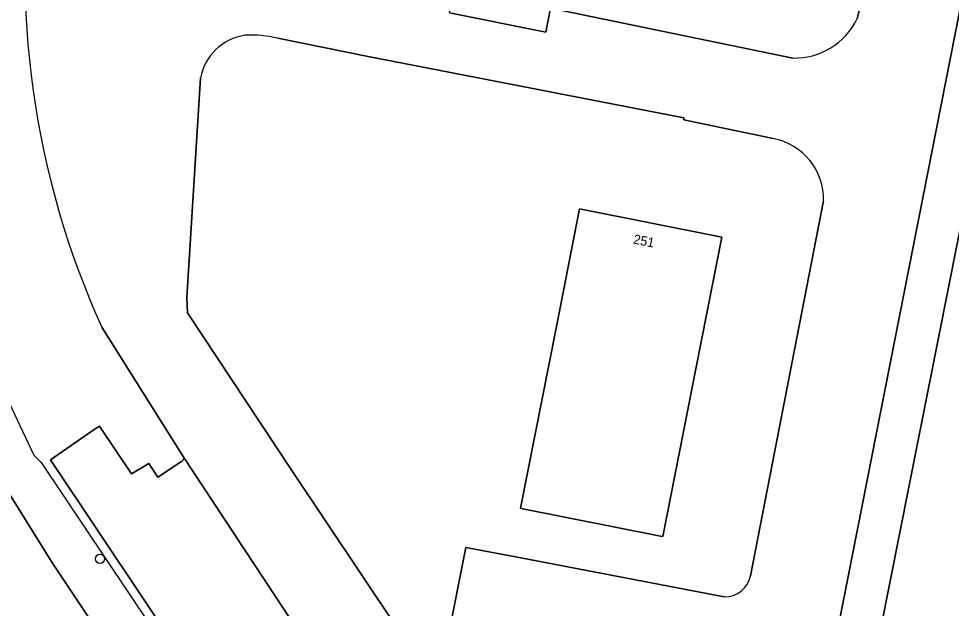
# Model space of a CAD drawing. Extents: x 158793 to 159888, y 384317 to 385256.
# Drawn here: x 159294 to 159393, y 384641.8 to 384704.4 of the extents above; entities that cross this region are included whole.
import ezdxf

# ---------------------------------------------------------------- set-up
doc = ezdxf.new("R2010")
doc.units = 0
for name, color, linetype in [('IMGEO_Berm_groen', 7, 'Continuous'), ('IMGEO_Boom', 7, 'Continuous'), ('IMGEO_Erf', 7, 'Continuous'), ('IMGEO_Groenvoorziening', 7, 'Continuous'), ('IMGEO_Hek', 7, 'Continuous'), ('IMGEO_Pand', 7, 'Continuous'), ('IMGEO_Pand_nummerreeks', 7, 'Continuous'), ('IMGEO_Parkeervlak_open', 7, 'Continuous'), ('IMGEO_Rijbaan_lokaal_gesloten', 7, 'Continuous'), ('IMGEO_Voetpad_open', 7, 'Continuous')]:
    doc.layers.add(name, color=color, linetype=linetype)

msp = doc.modelspace()

# ---------------------------------------------------------------- linework, layer by layer
at = {"layer": 'IMGEO_Berm_groen'}
msp.add_lwpolyline([(159333.494, 384583.345), (159340.335, 384575.84), (159343.091, 384578.482), (159297.497, 384646.725), (159292.522, 384654.756), (159285.647, 384666.91), (159278.91, 384680.193)], dxfattribs=at)
at = {"layer": 'IMGEO_Boom'}
msp.add_circle((159302.631, 384647.073), 0.489, dxfattribs=at)
at = {"layer": 'IMGEO_Erf'}
for points in [[(159374.089, 384691.673), (159364.589, 384693.665), (159364.601, 384693.879), (159331.106, 384700.379), (159321.51, 384702.312)], [(159313.29, 384698.113), (159311.832, 384674.807)], [(159371.682, 384645.285), (159379.439, 384685.054)], [(159311.832, 384674.807), (159311.915, 384673.194), (159322.922, 384656.565), (159337.783, 384634.349)], [(159338.72, 384634.515), (159341.448, 384648.274), (159346.548, 384647.313), (159368.894, 384643.043)]]:
    msp.add_lwpolyline(points, dxfattribs=at)
msp.add_lwpolyline([(159351.107, 384671.91), (159353.529, 384684.2), (159368.63, 384681.21), (159367.146, 384673.684), (159366.373, 384669.762), (159362.366, 384649.444), (159362.14, 384649.489), (159347.5, 384652.39), (159347.269, 384652.44)], close=True, dxfattribs=at)
for centre, radius, start, end in [((159318.85, 384697.015), 5.667, 98.5115, 168.83156), ((159318.695, 384690.356), 12.283, 76.74869, 93.1903), ((159372.885, 384685.228), 6.556, 358.47607, 79.4197), ((159368.964, 384645.81), 2.768, 268.55001, 349.05974)]:
    msp.add_arc(centre, radius, start, end, dxfattribs=at)
at = {"layer": 'IMGEO_Groenvoorziening'}
for points in [[(159259.345, 384775.845), (159258.476, 384779.062), (159246.475, 384781.347), (159238.159, 384778.066), (159249.737, 384750), (159261.949, 384720.397), (159274.24, 384690.602), (159274.429, 384690.144), (159278.91, 384680.193), (159285.647, 384666.91), (159292.522, 384654.756), (159297.497, 384646.725), (159343.091, 384578.482), (159343.747, 384579.11), (159344.133, 384578.71), (159340.698, 384575.458), (159343.371, 384572.63)], [(159311.46, 384657.947), (159302.815, 384671.649)], [(159361.521, 384557.604), (159362.312, 384556.684), (159363.352, 384557.381), (159364.038, 384557.841), (159360.749, 384562.76), (159347.62, 384582.396), (159327.44, 384612.577), (159297.356, 384657.569), (159302.122, 384660.871), (159302.57, 384661.155), (159305.956, 384656.085), (159307.806, 384657.199), (159308.755, 384655.741), (159311.27, 384657.413)]]:
    msp.add_lwpolyline(points, dxfattribs=at)
for centre, radius, start, end in [((159385.86, 384709.379), 91.215, 171.46871, 204.43394), ((159311.158, 384657.754), 0.359, 288.25757, 32.57078)]:
    msp.add_arc(centre, radius, start, end, dxfattribs=at)
at = {"layer": 'IMGEO_Hek'}
msp.add_lwpolyline([(159274.5, 384690.739), (159278.929, 384692.559), (159288.519, 384672.14), (159291.739, 384666.179), (159295.6, 384658.09), (159296.39, 384657.309), (159363.352, 384557.381)], dxfattribs=at)
at = {"layer": 'IMGEO_Pand'}
for points in [[(159339.73, 384705), (159349.94, 384702.969), (159350.44, 384705.486)], [(159396.73, 384696.179), (159374.239, 384582.909), (159398.809, 384578.09)]]:
    msp.add_lwpolyline(points, dxfattribs=at)
msp.add_lwpolyline([(159366.373, 384669.762), (159367.146, 384673.684), (159368.63, 384681.21), (159353.529, 384684.2), (159351.107, 384671.91), (159347.269, 384652.44), (159347.5, 384652.39), (159362.14, 384649.489), (159362.366, 384649.444)], close=True, dxfattribs=at)
at = {"layer": 'IMGEO_Parkeervlak_open'}
for points in [[(159375.084, 384714.387), (159376.059, 384719.309), (159366.249, 384721.252), (159354.049, 384723.669), (159350.44, 384705.486), (159376.165, 384700.213)], [(159382.997, 384704.388), (159384.634, 384710.887)], [(159311.27, 384657.413), (159308.755, 384655.741), (159307.806, 384657.199), (159305.956, 384656.085), (159302.57, 384661.155), (159302.122, 384660.871), (159297.356, 384657.569), (159327.44, 384612.577), (159333.099, 384616.361), (159333.285, 384616.081), (159365.154, 384567.946), (159369.445, 384561.464), (159372.753, 384556.485), (159383.254, 384540.805), (159386.325, 384542.862), (159387.316, 384543.526)], [(159355.537, 384591.604), (159337.281, 384618.767), (159311.46, 384657.947)]]:
    msp.add_lwpolyline(points, dxfattribs=at)
for centre, radius, start, end in [((159376.38, 384707.539), 7.329, 268.31979, 334.53799), ((159311.158, 384657.754), 0.359, 288.25757, 32.57078)]:
    msp.add_arc(centre, radius, start, end, dxfattribs=at)
at = {"layer": 'IMGEO_Rijbaan_lokaal_gesloten'}
for points in [[(159370.205, 384585.121), (159426.544, 384870.707)], [(159376.165, 384700.213), (159350.44, 384705.486), (159349.94, 384702.969), (159339.73, 384705), (159339.829, 384705.503), (159311.737, 384711.172), (159305.723, 384712.394), (159305.96, 384713.817), (159304.467, 384714.096)], [(159384.634, 384710.887), (159382.997, 384704.388)], [(159321.51, 384702.312), (159331.106, 384700.379), (159364.601, 384693.879), (159364.589, 384693.665), (159374.089, 384691.673)], [(159337.783, 384634.349), (159322.922, 384656.565), (159311.915, 384673.194), (159311.832, 384674.807), (159313.29, 384698.113)], [(159379.439, 384685.054), (159371.682, 384645.285)], [(159302.815, 384671.649), (159311.46, 384657.947), (159337.281, 384618.767), (159355.537, 384591.604), (159368.137, 384572.858), (159387.897, 384543.458), (159400.133, 384525.253), (159404.553, 384518.659), (159407.153, 384514.791), (159417.418, 384499.516), (159419.855, 384495.887), (159433.334, 384475.662), (159435.046, 384473.101), (159433.652, 384463.848), (159462.153, 384421.284), (159464.674, 384422.972), (159467.803, 384439.699), (159474.278, 384444.109), (159474.606, 384444.32)], [(159368.894, 384643.043), (159346.548, 384647.313), (159341.448, 384648.274), (159338.72, 384634.515)]]:
    msp.add_lwpolyline(points, dxfattribs=at)
for centre, radius, start, end in [((159385.86, 384709.379), 91.215, 171.46871, 204.43394), ((159376.38, 384707.539), 7.329, 268.31979, 334.53799), ((159318.85, 384697.015), 5.667, 98.5115, 168.83156), ((159318.695, 384690.356), 12.283, 76.74869, 93.1903), ((159372.885, 384685.228), 6.556, 358.47607, 79.4197), ((159368.964, 384645.81), 2.768, 268.55001, 349.05974)]:
    msp.add_arc(centre, radius, start, end, dxfattribs=at)
at = {"layer": 'IMGEO_Voetpad_open'}
for points in [[(159426.544, 384870.707), (159370.205, 384585.121)], [(159393.959, 384553.549), (159374.239, 384582.909), (159396.73, 384696.179)]]:
    msp.add_lwpolyline(points, dxfattribs=at)

# ---------------------------------------------------------------- texts
at = {"layer": 'IMGEO_Pand_nummerreeks'}
msp.add_text('251', height=1, rotation=348.60387, dxfattribs=at).set_placement((159359.18, 384680.537))

doc.saveas('drawing.dxf')
